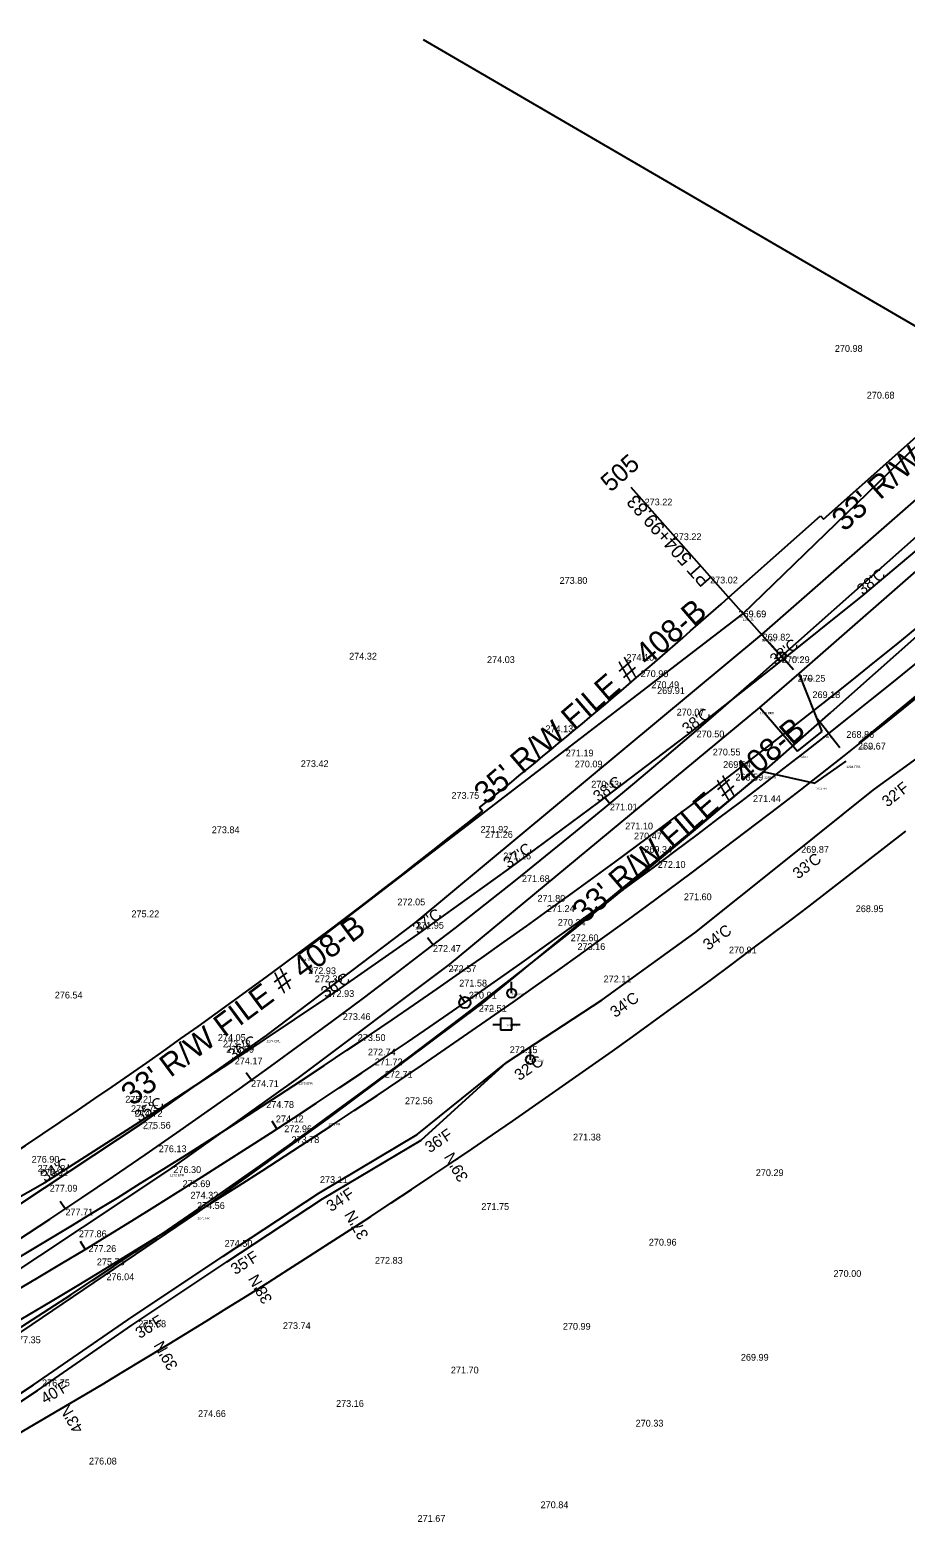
# Model space of a CAD drawing. Extents: x 49683 to 58852, y 49525 to 54803.
# Drawn here: x 52213 to 52600, y 50294 to 50960 of the extents above; entities that cross this region are included whole.
import ezdxf

# ---------------------------------------------------------------- set-up
doc = ezdxf.new("R2010")
doc.units = 0
for name, color, linetype in [('Level 1', 7, 'Continuous'), ('Level 11', 7, 'Continuous'), ('Level 12', 7, 'Continuous'), ('Level 13', 7, 'Continuous'), ('Level 18', 7, 'Continuous'), ('Level 19', 7, 'Continuous'), ('Level 20', 7, 'Continuous'), ('Level 21', 7, 'Continuous'), ('Level 25', 7, 'Continuous'), ('Level 3', 7, 'Continuous'), ('Level 32', 7, 'Continuous'), ('Level 33', 7, 'Continuous'), ('Level 48', 7, 'Continuous'), ('Level 51', 7, 'Continuous'), ('Level 53', 7, 'Continuous'), ('Level 58', 7, 'Continuous'), ('Level 59', 7, 'Continuous'), ('Level 61', 7, 'Continuous'), ('Level 8', 7, 'Continuous'), ('Level 9', 7, 'Continuous')]:
    doc.layers.add(name, color=color, linetype=linetype)

# ---------------------------------------------------------------- blocks, each defined once
blk = doc.blocks.new('GW')
at = {"layer": 'Level 9'}
blk.add_line((0, 0), (0, 5), dxfattribs=at)
blk.add_circle((0, 0), 2, dxfattribs=at)
blk = doc.blocks.new('PP')
at = {"layer": 'Level 9'}
for p, q in [((2.53, 2.45), (-2.47, 2.45)), ((-2.47, 2.45), (-2.47, -2.55)), ((2.53, -2.55), (2.53, 2.45)), ((-5.91, -0.11), (-2.44, -0.11)), ((-2.47, -2.55), (2.53, -2.55)), ((2.45, -0.11), (6.09, -0.11))]:
    blk.add_line(p, q, dxfattribs=at)

msp = doc.modelspace()

# ---------------------------------------------------------------- linework, layer by layer
at = {"layer": 'Level 1'}
for p, q in [((52544.81, 50683.3), (55534.58, 53340.86)), ((52543.48, 50684.8), (52478.41, 50758)), ((52544.94, 50683.42), (52539.62, 50689.4)), ((52550.25, 50677.44), (52544.94, 50683.42)), ((52469.06, 50618.29), (52466.5, 50621.38)), ((52390.95, 50555.86), (52388.5, 50559.03)), ((52310.71, 50496.19), (52308.38, 50499.44)), ((52228.44, 50439.35), (52226.22, 50442.68))]:
    msp.add_line(p, q, dxfattribs=at)
msp.add_circle((52544.81, 50683.3), 2, dxfattribs=at)
msp.add_arc((50641.56, 52824.47), 2864.78, 268.37962, 311.63333, dxfattribs=at)
at = {"layer": 'Level 11'}
for p, q in [((52579.25, 50645.17), (52882.73, 50895.61)), ((52527.71, 50702.05), (52634.35, 50805.36)), ((52331.92, 50551.79), (52527.71, 50702.05))]:
    msp.add_line(p, q, dxfattribs=at)
at = {"layer": 'Level 12'}
for p, q in [((52386.57, 50955.87), (52637.37, 50809.73)), ((52412.79, 50615.01), (52411.54, 50616.58))]:
    msp.add_line(p, q, dxfattribs=at)
at = {"layer": 'Level 13'}
for p, q in [((53407.7, 51406.16), (52566.74, 50658.64)), ((52563.41, 50743.99), (52637.37, 50809.73)), ((52521.55, 50709.46), (52562.08, 50745.49)), ((52562.08, 50745.49), (52563.41, 50743.99)), ((52411.54, 50616.58), (52412.79, 50615.01))]:
    msp.add_line(p, q, dxfattribs=at)
for radius, start, end in [(2829.79, 308.71775, 311.63328), (2897.79, 282.71776, 311.63339), (2831.79, 296.71776, 308.71775)]:
    msp.add_arc((50641.55, 52824.48), radius, start, end, dxfattribs=at)
at = {"layer": 'Level 18'}
for p, q in [((52580.75, 50710.21), (52618.52, 50742.07)), ((52542.19, 50679.3), (52580.75, 50710.21)), ((52503.34, 50648.76), (52542.19, 50679.3)), ((52585.47, 50624.39), (52626.4, 50654.08)), ((52463.98, 50618.85), (52503.34, 50648.76)), ((52546.13, 50592.72), (52585.47, 50624.39)), ((52424.24, 50589.46), (52463.98, 50618.85)), ((52506.55, 50561.32), (52546.13, 50592.72)), ((52384.1, 50560.6), (52424.24, 50589.46)), ((52343.53, 50532.34), (52384.1, 50560.6)), ((52465.61, 50531.73), (52506.55, 50561.32)), ((52302.48, 50504.77), (52343.53, 50532.34)), ((52423.39, 50503.96), (52465.61, 50531.73)), ((52261.1, 50477.68), (52302.48, 50504.77)), ((52383.91, 50472.17), (52423.39, 50503.96)), ((52385.63, 50469.7), (52423.39, 50503.96)), ((52219.41, 50451.04), (52261.1, 50477.68)), ((52340.46, 50446.27), (52383.91, 50472.17)), ((52342.05, 50443.73), (52385.63, 50469.7)), ((52176.45, 50426.49), (52219.41, 50451.04)), ((52298.23, 50418.53), (52340.46, 50446.27)), ((52299.89, 50416.02), (52342.05, 50443.73)), ((52256.18, 50390.42), (52298.23, 50418.53)), ((52257.87, 50387.94), (52299.89, 50416.02)), ((52214.48, 50361.59), (52256.18, 50390.42)), ((52216.16, 50359.11), (52257.87, 50387.94)), ((52172.09, 50333.76), (52214.48, 50361.59)), ((52173.7, 50331.23), (52216.16, 50359.11))]:
    msp.add_line(p, q, dxfattribs=at)
at = {"layer": 'Level 19'}
for p, q in [((52565.77, 50649.38), (52560.82, 50655.66)), ((52565.77, 50649.38), (52570.72, 50643.1)), ((52486.3, 50588.68), (52483.92, 50591.9)), ((52405.02, 50530.44), (52402.74, 50533.73)), ((52321.99, 50474.71), (52319.81, 50478.07)), ((52237.3, 50421.55), (52235.23, 50424.97))]:
    msp.add_line(p, q, dxfattribs=at)
msp.add_circle((52405.02, 50530.44), 2.5, dxfattribs=at)
msp.add_arc((50539, 53220.69), 3274.06, 284.51284, 311.63337, dxfattribs=at)
at = {"layer": 'Level 20'}
for radius in [3262.06, 3286.06]:
    msp.add_arc((50539, 53220.69), radius, 284.51246, 311.63318, dxfattribs=at)
at = {"layer": 'Level 3'}
for p, q in [((52536.19, 50693.05), (52657.35, 50799.14)), ((52552.71, 50675.77), (52668.7, 50777.53)), ((52383.07, 50565.65), (52536.19, 50693.05)), ((52535.34, 50660.73), (52552.71, 50675.77)), ((52398.28, 50547.35), (52535.34, 50660.73)), ((52317.4, 50515.97), (52383.07, 50565.65)), ((52331.52, 50497.22), (52398.28, 50547.35)), ((52262.41, 50477.27), (52317.4, 50515.97)), ((52274.71, 50456.75), (52331.52, 50497.22)), ((52176.97, 50420.76), (52262.41, 50477.27)), ((52192.62, 50402.34), (52274.71, 50456.75))]:
    msp.add_line(p, q, dxfattribs=at)
at = {"layer": 'Level 33'}
msp.add_arc((50539, 53220.69), 3329.06, 284.51246, 308.24612, dxfattribs=at)
at = {"layer": 'Level 8'}
for p, q in [((52562.88, 50650.26), (52552.71, 50675.77)), ((52535.34, 50660.73), (52551.99, 50641.44)), ((52551.99, 50641.44), (52562.88, 50650.26)), ((52559.58, 50627.44), (52573.52, 50637.05)), ((52412.59, 50530.13), (52537.26, 50632.33)), ((52537.26, 50632.33), (52559.58, 50627.44)), ((52344.69, 50479.28), (52412.59, 50530.13)), ((52286.9, 50437.81), (52344.69, 50479.28)), ((52204.78, 50382.12), (52286.9, 50437.81))]:
    msp.add_line(p, q, dxfattribs=at)

# ---------------------------------------------------------------- block references
at = {"layer": 'Level 9'}
for name, p in [('GW', (52425.65, 50534.62)), ('PP', (52423.29, 50520.92)), ('GW', (52433.95, 50505.2))]:
    msp.add_blockref(name, p, dxfattribs=at)

# ---------------------------------------------------------------- texts
at = {"layer": 'Level 1'}
msp.add_text('PT 504+99.83', height=6, rotation=131.63333, dxfattribs=at).set_placement((52514.08, 50717.4))
at = {"layer": 'Level 21'}
msp.add_text('505', height=8, rotation=41.63333, dxfattribs=at).set_placement((52469.43, 50755.59))
at = {"layer": 'Level 25'}
for s, rotation, p in [("33' R/W FILE # 408-B", 41.63333, (52572.62, 50738.12)), ("35' R/W FILE # 408-B", 40.74622, (52414.47, 50617.41)), ("33' R/W FILE # 408-B", 40.72213, (52457.9, 50565.13)), ("33' R/W FILE # 408-B", 36.5988, (52257.95, 50484.53))]:
    msp.add_text(s, height=10, rotation=rotation, dxfattribs=at).set_placement(p)
at = {"layer": 'Level 32'}
for s, p in [('270.98', (52568.44, 50817.86)), ('270.68', (52582.55, 50797.22)), ('273.22', (52484.4, 50750.05)), ('273.22', (52497.26, 50734.72)), ('273.80', (52446.85, 50715.4)), ('273.02', (52513.33, 50715.57)), ('269.69', (52525.85, 50700.63)), ('269.69', (52525.9, 50700.58)), ('269.82', (52536.52, 50690.34)), ('274.32', (52353.88, 50681.95)), ('274.03', (52414.8, 50680.43)), ('274.10', (52476.36, 50681.43)), ('270.29', (52545.04, 50680.43)), ('270.90', (52482.63, 50674.21)), ('270.49', (52487.39, 50669.32)), ('270.25', (52552.01, 50672.2)), ('269.91', (52489.93, 50666.75)), ('269.18', (52558.57, 50664.94)), ('270.07', (52498.57, 50657.24)), ('274.13', (52440.6, 50649.87)), ('270.50', (52507.36, 50647.59)), ('268.86', (52573.54, 50647.39)), ('271.19', (52449.59, 50639.21)), ('270.55', (52514.51, 50639.61)), ('269.67', (52578.68, 50642.22)), ('273.42', (52332.53, 50634.47)), ('270.09', (52453.54, 50634.33)), ('269.64', (52519.11, 50634.11)), ('270.53', (52460.84, 50625.42)), ('268.59', (52524.52, 50628.54)), ('273.75', (52399.08, 50620.46)), ('271.44', (52532.29, 50619.07)), ('271.01', (52469.07, 50615.34)), ('273.84', (52293.19, 50605.27)), ('271.92', (52411.91, 50605.47)), ('271.26', (52413.91, 50603.24)), ('271.10', (52475.85, 50606.95)), ('270.47', (52479.73, 50602.53)), ('269.34', (52484.27, 50596.63)), ('269.87', (52553.57, 50596.62)), ('271.16', (52421.96, 50593.73)), ('272.10', (52490.23, 50589.95)), ('271.68', (52430.23, 50583.71)), ('272.05', (52375.21, 50573.42)), ('271.80', (52437.09, 50575.02)), ('271.24', (52441.24, 50570.47)), ('271.60', (52501.76, 50575.69)), ('268.95', (52577.68, 50570.41)), ('275.22', (52257.72, 50568.16)), ('271.95', (52383.47, 50563.1)), ('270.24', (52446.06, 50564.4)), ('272.60', (52451.76, 50557.57)), ('272.47', (52390.91, 50552.84)), ('273.16', (52454.76, 50553.69)), ('270.91', (52521.66, 50552.18)), ('272.93', (52335.8, 50543.02)), ('272.57', (52397.79, 50543.91)), ('272.30', (52338.7, 50539.48)), ('271.58', (52402.51, 50537.56)), ('272.11', (52466.3, 50539.41)), ('276.54', (52223.85, 50532.28)), ('272.93', (52343.85, 50532.97)), ('270.91', (52406.77, 50532.22)), ('272.51', (52411.2, 50526.45)), ('273.46', (52351.07, 50522.76)), ('274.05', (52295.91, 50513.54)), ('273.13', (52298.14, 50510.74)), ('273.50', (52357.69, 50513.5)), ('273.59', (52299.61, 50508.36)), ('274.17', (52303.35, 50503.21)), ('272.74', (52362.18, 50507.13)), ('272.15', (52424.82, 50508.14)), ('271.72', (52365.23, 50502.77)), ('272.71', (52369.65, 50497.31)), ('274.71', (52310.55, 50493.2)), ('275.21', (52255, 50486.28)), ('274.78', (52317.26, 50483.94)), ('272.56', (52378.54, 50485.6)), ('273.75', (52257.52, 50482.11)), ('274.72', (52259.18, 50480.09)), ('274.12', (52321.53, 50477.6)), ('275.56', (52262.78, 50474.79)), ('272.96', (52325.22, 50473.23)), ('271.38', (52452.79, 50469.57)), ('276.13', (52269.78, 50464.4)), ('273.78', (52328.41, 50468.42)), ('276.90', (52213.61, 50459.74)), ('274.72', (52216.26, 50455.76)), ('275.92', (52217.39, 50453.98)), ('276.30', (52276.23, 50455.19)), ('273.11', (52340.99, 50450.8)), ('270.29', (52533.54, 50453.84)), ('277.09', (52221.62, 50446.98)), ('275.69', (52280.31, 50448.96)), ('274.32', (52283.81, 50443.89)), ('277.71', (52228.54, 50436.46)), ('274.56', (52286.67, 50439.33)), ('271.75', (52412.29, 50438.9)), ('277.86', (52234.49, 50426.85)), ('270.96', (52486.27, 50423.14)), ('277.26', (52238.73, 50420.34)), ('274.50', (52298.87, 50422.62)), ('275.75', (52242.45, 50414.45)), ('272.83', (52365.27, 50415.12)), ('276.04', (52246.66, 50407.86)), ('270.00', (52567.86, 50409.31)), ('275.68', (52260.75, 50387.1)), ('273.74', (52324.61, 50386.29)), ('270.99', (52448.3, 50385.98)), ('277.35', (52205.36, 50380.03)), ('269.99', (52526.93, 50372.31)), ('271.70', (52398.82, 50366.67)), ('276.75', (52218.23, 50361.01)), ('273.16', (52348.11, 50351.91)), ('274.66', (52287.14, 50347.46)), ('270.33', (52480.45, 50343.2)), ('276.08', (52238.96, 50326.46)), ('270.84', (52438.46, 50307.17)), ('271.67', (52384.12, 50301.13))]:
    msp.add_text(s, height=3, dxfattribs=at).set_placement(p)
at = {"layer": 'Level 48'}
for s, rotation, p in [("38'C", 39.1211, (52580.75, 50710.21)), ("38'C", 38.24611, (52542.19, 50679.3)), ("38'C", 37.37114, (52503.34, 50648.76)), ("38'C", 36.49614, (52463.98, 50618.85)), ("32'F", 38.24614, (52591.66, 50616.54)), ("37'C", 35.62116, (52424.24, 50589.46)), ("33'C", 37.37113, (52552.2, 50584.78)), ("37'C", 34.74614, (52384.1, 50560.6)), ("34'C", 36.49611, (52512.5, 50553.28)), ("36'C", 33.87112, (52343.53, 50532.34)), ("34'C", 35.62112, (52471.43, 50523.6)), ("36'C", 32.99613, (52302.48, 50504.77)), ("32'C", 34.74613, (52429.09, 50495.74)), ("35'C", 32.12112, (52261.1, 50477.68)), ("36'F", 33.87112, (52389.49, 50463.87)), ("34'C", 31.24615, (52219.41, 50451.04)), ("39'N", 119.91701, (52406.69, 50453.14)), ("34'F", 32.99616, (52345.9, 50437.89)), ("37'N", 119.91701, (52362.65, 50427.62)), ("35'F", 32.12117, (52303.55, 50410.06)), ("38'N", 119.91701, (52320.15, 50399.27)), ("36'F", 31.24615, (52261.37, 50381.88)), ("39'N", 119.91701, (52278.42, 50369.88)), ("40'F", 30.37114, (52219.54, 50352.97)), ("43'N", 119.91701, (52236.69, 50342.04))]:
    msp.add_text(s, height=5, rotation=rotation, dxfattribs=at).set_placement(p)
at = {"layer": 'Level 51'}
msp.add_text('8 PT 504+99.83', height=1, dxfattribs=at).set_placement((52544.81, 50682.3))
at = {"layer": 'Level 53'}
for s, p in [('1295 EPL', (52536.19, 50690.05)), ('1300 EPR', (52552.71, 50672.77)), ('1296 EPR', (52535.34, 50657.73)), ('1285 EPL', (52383.07, 50562.65)), ('1286 EPR', (52398.28, 50544.36)), ('1274 EPL', (52317.4, 50512.97)), ('1275 EPR', (52331.52, 50494.22)), ('1273 EPL', (52262.41, 50474.27)), ('1272 EPR', (52274.71, 50453.75))]:
    msp.add_text(s, height=1, dxfattribs=at).set_placement(p)
at = {"layer": 'Level 58'}
for s, p in [('1301 DB', (52552.71, 50672.77)), ('1297 DA', (52535.34, 50657.73)), ('1299 D', (52562.88, 50647.26)), ('1298 D', (52551.99, 50638.44)), ('1294 FRB', (52573.52, 50634.05)), ('1292 FR', (52537.26, 50629.33)), ('1293 FR', (52559.58, 50624.44)), ('1287 FR', (52412.59, 50527.13)), ('1276 FR', (52344.69, 50476.28)), ('1271 FR', (52286.9, 50434.81))]:
    msp.add_text(s, height=1, dxfattribs=at).set_placement(p)
at = {"layer": 'Level 59'}
for s, p in [('1288 GW', (52425.65, 50533.62)), ('1289 PP', (52423.29, 50519.92)), ('1290 GW', (52433.95, 50504.2))]:
    msp.add_text(s, height=1, dxfattribs=at).set_placement(p)
at = {"layer": 'Level 61'}
for s, p in [('1291 TL', (52527.71, 50699.05)), ('1302 TRA', (52579.25, 50642.17)), ('1284 TLA', (52331.92, 50548.79))]:
    msp.add_text(s, height=1, dxfattribs=at).set_placement(p)

doc.saveas('drawing.dxf')
